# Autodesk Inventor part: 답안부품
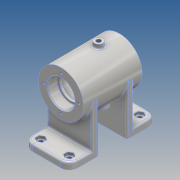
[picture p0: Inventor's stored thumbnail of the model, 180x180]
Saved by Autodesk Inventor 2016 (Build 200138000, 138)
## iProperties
Created: 2017-02
Part Number: 답안부품
Material: 알루미늄 6061
Document SubType Name: Modeling
Designer: Administrator
Density: 2.7 g/cm^3
Appearance: 알루미늄 - 평지
Mass: 354.751 g
Surface Area: 422.76 cm^2
Volume: 131.389 cm^3
Author: Administrator
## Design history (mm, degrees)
sketch "스케치1"
  geometry: L1 (0, 0)-(54, 0); L2 (54, 104)-(0, 104); L3 (0, 69)-(54, 69); L4 (0, 35)-(54, 35); L5 (0, 104)-(0, 69); L6 (0, 35)-(0, 0); L7 (54, 0)-(54, 35); L8 (54, 69)-(54, 104)
  constraints: 16 end point, 5 parallel, 2 perpendicular, 1 horizontal
  dimensions: "d0" = 54 distance of L2.end L2.start; "d1" = 104 distance of L2.start L1.end; "d4" = 35 distance between parallel lines of L1 L4; "d5" = 54 distance between parallel lines of L6 L7; "d6" = 69 distance between parallel lines of L3 L1; "d7" = 54 distance between parallel lines of L6 L8
extrude "돌출1" new body sketch "스케치1" distance "d8" = 8; taper "d9" = 0 deg
node "작업 평면1"
sketch "스케치2"
  geometry: L1 (8, -69)-(0, -69) reference; L2 (0, -69)-(0, -34) reference; L3 (0, -34)-(8, -34) reference; L4 (8, -34)-(8, -69) reference; L5 (0, 35)-(8, 35) reference; L6 (8, 35)-(8, 0) reference; L7 (8, 0)-(0, 0) reference; L8 (0, 0)-(0, 35) reference; L9 (0, -69)-(0, -34) reference; L10 (60, 18)-(60, -52); L11 (60, -52)-(87, -52); L12 (87, -52)-(87, 18); L13 (87, 18)-(60, 18)
  constraints: 8 end point, 1 horizontal, 1 perpendicular, 1 vertical
  dimensions: "d11" = 70 distance of L10.start L10.end; "d12" = 27 distance of L10.end L11.end; "d13" = 70 distance of L11.end L12.end; "d14" = 60 distance between parallel lines of L8 L10; "d15" = 52 distance between parallel lines of L7 L11
revolve "회전1" sketch "스케치2" stored, may be unused: angle "d16" = 90 deg
sketch "스케치3"
  geometry: L1 (0, 69)-(54, 69) reference; L2 (54, 104)-(54, 69) reference; L3 (54, 69)-(0, 69) reference; L4 (0, 69)-(0, 104) reference; L5 (0, 104)-(54, 104) reference; L6 (0, 0)-(0, 35) reference; L7 (0, 35)-(54, 35) reference; L8 (54, 35)-(54, 0) reference; L9 (54, 0)-(0, 0) reference; L10 (54, 77)-(0, 77); L11 (0, 104)-(0, 69) reference; L12 (0, 35)-(0, 0) reference; L13 (0, 27)-(54, 27); L14 (54, 0)-(54, 35) reference; L15 (54, 27)-(54, 35); L16 (54, 35)-(0, 35) reference; L17 (54, 35)-(0, 35); L18 (0, 35)-(0, 27); L19 (0, 77)-(0, 69); L20 (0, 69)-(54, 69) reference; L21 (0, 69)-(54, 69); L22 (54, 69)-(54, 77)
  constraints: 16 end point, 4 point on line, 3 collinear, 3 perpendicular, 1 horizontal, 1 vertical
  dimensions: "d17" = 8 distance between parallel lines of L1 L10; "d18" = 8 distance between parallel lines of L7 L13
extrude "돌출2" join sketch "스케치3" stored distance "d19" = 8; taper "d20" = 0 deg
node "작업 평면2"
sketch "스케치4"
  geometry: L1 (0, 35)-(8, 35) reference; L2 (8, 35)-(8, 8) reference; L3 (8, 8)-(33, 8) reference; L4 (33, 8)-(33, 18) reference; L5 (33, 18)-(87, 18) reference; L6 (87, 18)-(87, -52) reference; L7 (87, -52)-(33, -52) reference; L8 (33, -52)-(33, -42) reference; L9 (33, -42)-(8, -42) reference; L10 (8, -42)-(8, -69) reference; L11 (8, -69)-(0, -69) reference; L12 (0, -69)-(0, -34) reference; L13 (0, -34)-(33, -34) reference; L14 (33, -34)-(33, 0) reference; L15 (33, 0)-(0, 0) reference; L16 (0, 0)-(0, 35) reference; L17 (60, 18)-(60, -52); L18 (33, -52)-(87, -52) reference; L19 (60, -52)-(76, -52); L20 (76, -52)-(76, -40); L21 (76, -40)-(74, -40); L22 (74, -40)-(74, -37); L23 (74, -37)-(82, -37); L24 (82, -37)-(82, 3); L25 (82, 3)-(74, 3); L26 (74, 3)-(74, 6); L27 (74, 6)-(76, 6); L28 (76, 6)-(76, 18); L29 (76, 18)-(60, 18); L30 (33, 18)-(87, 18) reference
  constraints: 24 end point, 6 perpendicular, 4 point on line, 2 midpoint, 1 collinear, 1 horizontal
  dimensions: "d21" = 16 distance of L17.end L19.end; "d22" = 12 distance of L19.end L20.end; "d23" = 2 distance of L20.end L21.end; "d24" = 3 distance of L21.end L22.end; "d25" = 8 distance of L22.end L23.end; "d26" = 40 distance of L23.end L24.end; "d27" = 8 distance of L24.end L25.end; "d28" = 3 distance of L25.end L26.end; "d29" = 2 distance of L26.end L27.end
revolve "회전2" sketch "스케치4" stored, may be unused: angle "d30" = 90 deg
node "작업 평면3"
sketch "스케치5"
  geometry: L1 (-54, 87)-(0, 87) reference; L2 (-54, 77)-(-54, 104) reference; C1 r 5 at (-27, 62); 1 further point
  constraints: 1 centre point
  dimensions: "d33" = 10 diameter of C1; "d34" = 25 distance from line of L1 C1.centre; "d35" = 27 distance from line of L2 C1.centre
extrude "돌출3" join sketch "스케치5" stored distance "d36" = 8; taper "d37" = 0 deg
sketch "스케치6"
  geometry: C1 r 5 at (0, 0) reference; 1 further point
hole "구멍1" sketch "스케치6" at (0, 0) diameter "d38" = 5.188; stored, may be unused: countersink angle "d42" = 90 deg, drill point angle "d44" = 118 deg; dims "d39" = 12, "d40" = 4, "d41" = 2, "d43" = 15
sketch "스케치7" dims "d45" = 42
  geometry: C1 r 16 at (0, 0) reference; C2 r 27 at (0, 0) reference; 3 further points
  constraints: 2 vertical alignment, 1 coincident, 2 other
hole "구멍2" sketch "스케치7" at (0, -21) diameter "d46" = 3.242; stored, may be unused: countersink angle "d50" = 90 deg, drill point angle "d52" = 118 deg; dims "d47" = 8, "d48" = 4, "d49" = 2, "d51" = 10
sketch "스케치8" dims "d56" = 42
  geometry: C1 r 16 at (0, 0) reference; C2 r 27 at (0, 0) reference; 3 further points
  constraints: 2 vertical alignment, 1 coincident, 2 other
hole "구멍3" sketch "스케치8" at (0, 21) diameter "d57" = 3.242; stored, may be unused: countersink angle "d61" = 90 deg, drill point angle "d63" = 118 deg; dims "d58" = 8, "d59" = 4, "d60" = 2, "d62" = 10
sketch "스케치9" dims "d67" = 9, "d68" = 9, "d69" = 9, "d70" = 9
  geometry: L1 (54, 77)-(54, 104) reference; L2 (54, 104)-(0, 104) reference; L3 (0, 104)-(0, 77) reference; L4 (0, 77)-(54, 77) reference; L5 (54, 104)-(54, 77) reference; L6 (0, 104)-(54, 104) reference; L7 (0, 77)-(0, 104) reference; L8 (0, 69)-(0, 77) reference; L9 (54, 69)-(0, 69) reference; L10 (54, 77)-(54, 69) reference; L11 (54, 27)-(0, 27) reference; L12 (0, 0)-(0, 27) reference; L13 (54, 0)-(0, 0) reference; L14 (54, 27)-(54, 0) reference; L15 (54, 35)-(54, 27) reference; L16 (0, 35)-(54, 35) reference; L17 (0, 27)-(0, 35) reference; L18 (14.5, 91.402)-(10, 88.804); L19 (10, 88.804)-(5.5, 91.402); L20 (5.5, 91.402)-(5.5, 96.598); L21 (5.5, 96.598)-(10, 99.196); L22 (10, 99.196)-(14.5, 96.598); L23 (14.5, 96.598)-(14.5, 91.402); L24 (48.5, 91.402)-(44, 88.804); L25 (44, 88.804)-(39.5, 91.402); L26 (39.5, 91.402)-(39.5, 96.598); L27 (39.5, 96.598)-(44, 99.196); L28 (44, 99.196)-(48.5, 96.598); L29 (48.5, 96.598)-(48.5, 91.402); L30 (14.5, 7.402)-(10, 4.804); L31 (10, 4.804)-(5.5, 7.402); L32 (5.5, 7.402)-(5.5, 12.598); L33 (5.5, 12.598)-(10, 15.196); L34 (10, 15.196)-(14.5, 12.598); L35 (14.5, 12.598)-(14.5, 7.402); L36 (48.5, 7.402)-(44, 4.804); L37 (44, 4.804)-(39.5, 7.402); L38 (39.5, 7.402)-(39.5, 12.598); L39 (39.5, 12.598)-(44, 15.196); L40 (44, 15.196)-(48.5, 12.598); L41 (48.5, 12.598)-(48.5, 7.402); 12 further points
  constraints: 48 end point, 4 coincident, 4 horizontal alignment, 4 midpoint, 2 point on line, 60 other
  dimensions: "d71" = 10 distance from line of L2 point (10, 94); "d72" = 10 distance from line of L2 point (44, 94); "d73" = 10 distance from line of L13 point (10, 10); "d74" = 10 distance from line of L13 point (44, 10); "d75" = 10 distance from line of L3 point (10, 94); "d76" = 10 distance from line of L1 point (44, 94); "d77" = 10 distance from line of L12 point (10, 10); "d78" = 10 distance from line of L14 point (44, 10); "d79" = 60 deg angle of L3 L21; "d80" = 150 deg angle of L2 L28
extrude "돌출4" cut sketch "스케치9" distance "d81" = 3; taper "d82" = 0 deg
sketch "스케치10"
  geometry: L1 (14.5, 12.598)-(14.5, 7.402) reference; L2 (14.5, 12.598)-(10, 15.196) reference; L3 (10, 15.196)-(5.5, 12.598) reference; L4 (5.5, 12.598)-(5.5, 7.402) reference; L5 (5.5, 7.402)-(10, 4.804) reference; L6 (10, 4.804)-(14.5, 7.402) reference; L7 (14.5, 7.402)-(14.5, 12.598) reference; L8 (14.5, 96.598)-(10, 99.196) reference; L9 (10, 99.196)-(5.5, 96.598) reference; L10 (5.5, 96.598)-(5.5, 91.402) reference; L11 (5.5, 91.402)-(10, 88.804) reference; L12 (10, 88.804)-(14.5, 91.402) reference; L13 (14.5, 91.402)-(14.5, 96.598) reference; L14 (48.5, 96.598)-(44, 99.196) reference; L15 (44, 99.196)-(39.5, 96.598) reference; L16 (39.5, 96.598)-(39.5, 91.402) reference; L17 (39.5, 91.402)-(44, 88.804) reference; L18 (44, 88.804)-(48.5, 91.402) reference; L19 (48.5, 91.402)-(48.5, 96.598) reference; L20 (48.5, 12.598)-(44, 15.196) reference; L21 (44, 15.196)-(39.5, 12.598) reference; L22 (39.5, 12.598)-(39.5, 7.402) reference; L23 (39.5, 7.402)-(44, 4.804) reference; L24 (44, 4.804)-(48.5, 7.402) reference; L25 (48.5, 7.402)-(48.5, 12.598) reference; L26 (0, 0)-(0, 35) reference; L27 (0, 35)-(54, 35) reference; L28 (54, 35)-(54, 0) reference; L29 (54, 0)-(0, 0) reference; L30 (54, 104)-(54, 69) reference; L31 (54, 69)-(0, 69) reference; L32 (0, 69)-(0, 104) reference; L33 (0, 104)-(54, 104) reference; C1 r 2.5 at (10, 10); C2 r 2.5 at (44, 10); C3 r 2.5 at (44, 94); C4 r 2.5 at (10, 94)
  constraints: 4 centre point
  dimensions: "d83" = 5 diameter of C1; "d84" = 5 diameter of C2; "d85" = 5 diameter of C3; "d86" = 5 diameter of C4; "d87" = 4.5 distance from line of L13 C4.centre; "d88" = 5.19615 distance of L8.end C4.centre; "d89" = 4.5 distance from line of L1 C1.centre; "d90" = 5.19615 distance of L2.end C1.centre; "d91" = 4.5 distance from line of L25 C2.centre; "d92" = 5.19615 distance of L20.end C2.centre; "d93" = 4.5 distance from line of L19 C3.centre; "d94" = 5.19615 distance of L14.end C3.centre
extrude "돌출5" cut sketch "스케치10" stored distance "d95" = 3; taper "d96" = 0 deg
node "작업 평면4"
sketch "스케치11"
  geometry: L1 (0, 0)-(27, 0); L2 (0, 0)-(27, 0); L3 (0, 0)-(30, 0); L4 (19.37, -18.81)-(21.371, -21.892); L5 (16.339, -25.16)-(21.371, -21.892); L6 (-27, -60)-(-27, 0) reference; L7 (-27, -60)-(27, -60) reference; L8 (16.339, -25.16)-(14.705, -22.644); C1 r 22 at (0, 0) reference; C2 r 22 at (0, 0) reference; C3 r 27 at (0, 0) reference; C4 r 22 at (0, 0) reference; C5 r 27 at (0, 0) reference; A1 r 27 centre (0, 0) between (14.705, -22.644) and (19.37, -18.81); 1 further point
  constraints: 12 end point, 3 horizontal, 2 point on circle, 1 centre point, 1 coincident, 1 horizontal alignment, 1 point on line, 2 other
  dimensions: "d104" = 30 distance from line of C1.centre L5; "d105" = 6 distance from line of point (0, 0) L4; "d107" = 33 deg angle of L7 L5; "d108" = 33 deg angle of L6 L4; "d109" = 57 deg angle of L7 L8; "d110" = 1.63392 horizontal distance of L5.start L8.end
revolve "회전3" sketch "스케치11" stored, may be unused: angle "d111" = 90 deg
sketch "스케치12"
  geometry: C1 r 6 at (0, 0) reference; 1 further point
hole "구멍4" sketch "스케치12" at (0, 0) diameter "d112" = 5.188; stored, may be unused: countersink angle "d116" = 90 deg, drill point angle "d118" = 118 deg; dims "d113" = 16, "d114" = 4, "d115" = 2, "d117" = 20
fillet "모깎기1" dims "d119" = 2
fillet "모깎기2" dims "d120" = 10
fillet "모깎기3" dims "d121" = 2
fillet "모깎기4" dims "d122" = 2
fillet "모깎기5" dims "d123" = 2
fillet "모깎기6" dims "d124" = 0.3
fillet "모깎기7" dims "d125" = 3
chamfer "모따기1" distance "d126" = 1; stored, may be unused: second distance "d127" = 2, angle "d128" = 45 deg
sketch "스케치13"
  geometry: L1 (-27, 16)-(-27, -54) reference; L2 (27, 16)-(27, -54) reference; L3 (-27, -54)-(27, -54) reference; L4 (-27, 16)-(27, 16) reference; L5 (2.402, -2.408)-(2.402, -35.592); L6 (2.402, -35.592)-(-2.402, -35.592); L7 (-2.402, -35.592)-(-2.402, -2.408); L8 (-2.402, -2.408)-(2.402, -2.408); 1 further point
  constraints: 2 other
feature "엠보싱1" sketch "스케치13" dims "d0" = 54, "d1" = 104, "d4" = 35, "d5" = 54, "d6" = 69, "d7" = 54, "d130" = 0.5, "d131" = 0
fillet "모깎기8" dims "d132" = 2
node "솔리드1"
pattern_circular "원형 패턴1" dims angle "d54" = 360 deg
pattern_circular "원형 패턴2" dims angle "d65" = 360 deg
node "절단 모서리 투영1"
node "절단 모서리 투영2"
node "절단 모서리 투영3"
node "절단 모서리 투영4"
node "절단 모서리 투영5"
node "절단 모서리 투영6"
node "절단 모서리 투영7"
node "절단 모서리 투영8"
other parameters: "d31" = -92, "d100" = 57 deg
